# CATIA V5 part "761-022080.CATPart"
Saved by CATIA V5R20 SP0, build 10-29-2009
Part number: 761-022080
Source: Unknown
Property "ARTICLENO": "761-022080"
Property "BOMINFO": "761-022080"
Property "CODE": "761-022080"
Property "H": "22.000"
Property "L1": "80.000"
Property "L2": "50.000"
Property "LINA": "761-022080"
Property "NB": "761-022080"
Property "NBSYN": "$CODE."
Property "NN": "761"
Property "NT": "VW/AUDI Keys"
Property "P": "4.000"
Property "SUPPLIER": "CF"
Bounding box of the stored display mesh (mm): x -40 to 40, y 0 to 22, z -11 to 11
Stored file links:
  C:\Users\Utente\Desktop\3D files 761\761-022080.CATPart
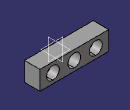
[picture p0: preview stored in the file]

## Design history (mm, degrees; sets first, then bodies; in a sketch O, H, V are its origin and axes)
Body1 "Geometry.1" (main body)
  Solid1 "761-022080.catpart": solid without history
